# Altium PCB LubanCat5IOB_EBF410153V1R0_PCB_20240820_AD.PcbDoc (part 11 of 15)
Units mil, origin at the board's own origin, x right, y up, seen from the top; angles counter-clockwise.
Board outline 6811.02 x 4055.12 mil, 6 copper layers (TOP, GND02, ART03, ART04, PWR05, BOTTOM), stack 59.279 mil thick; 981 components, 783 nets, 3627 pads, 2669 vias.
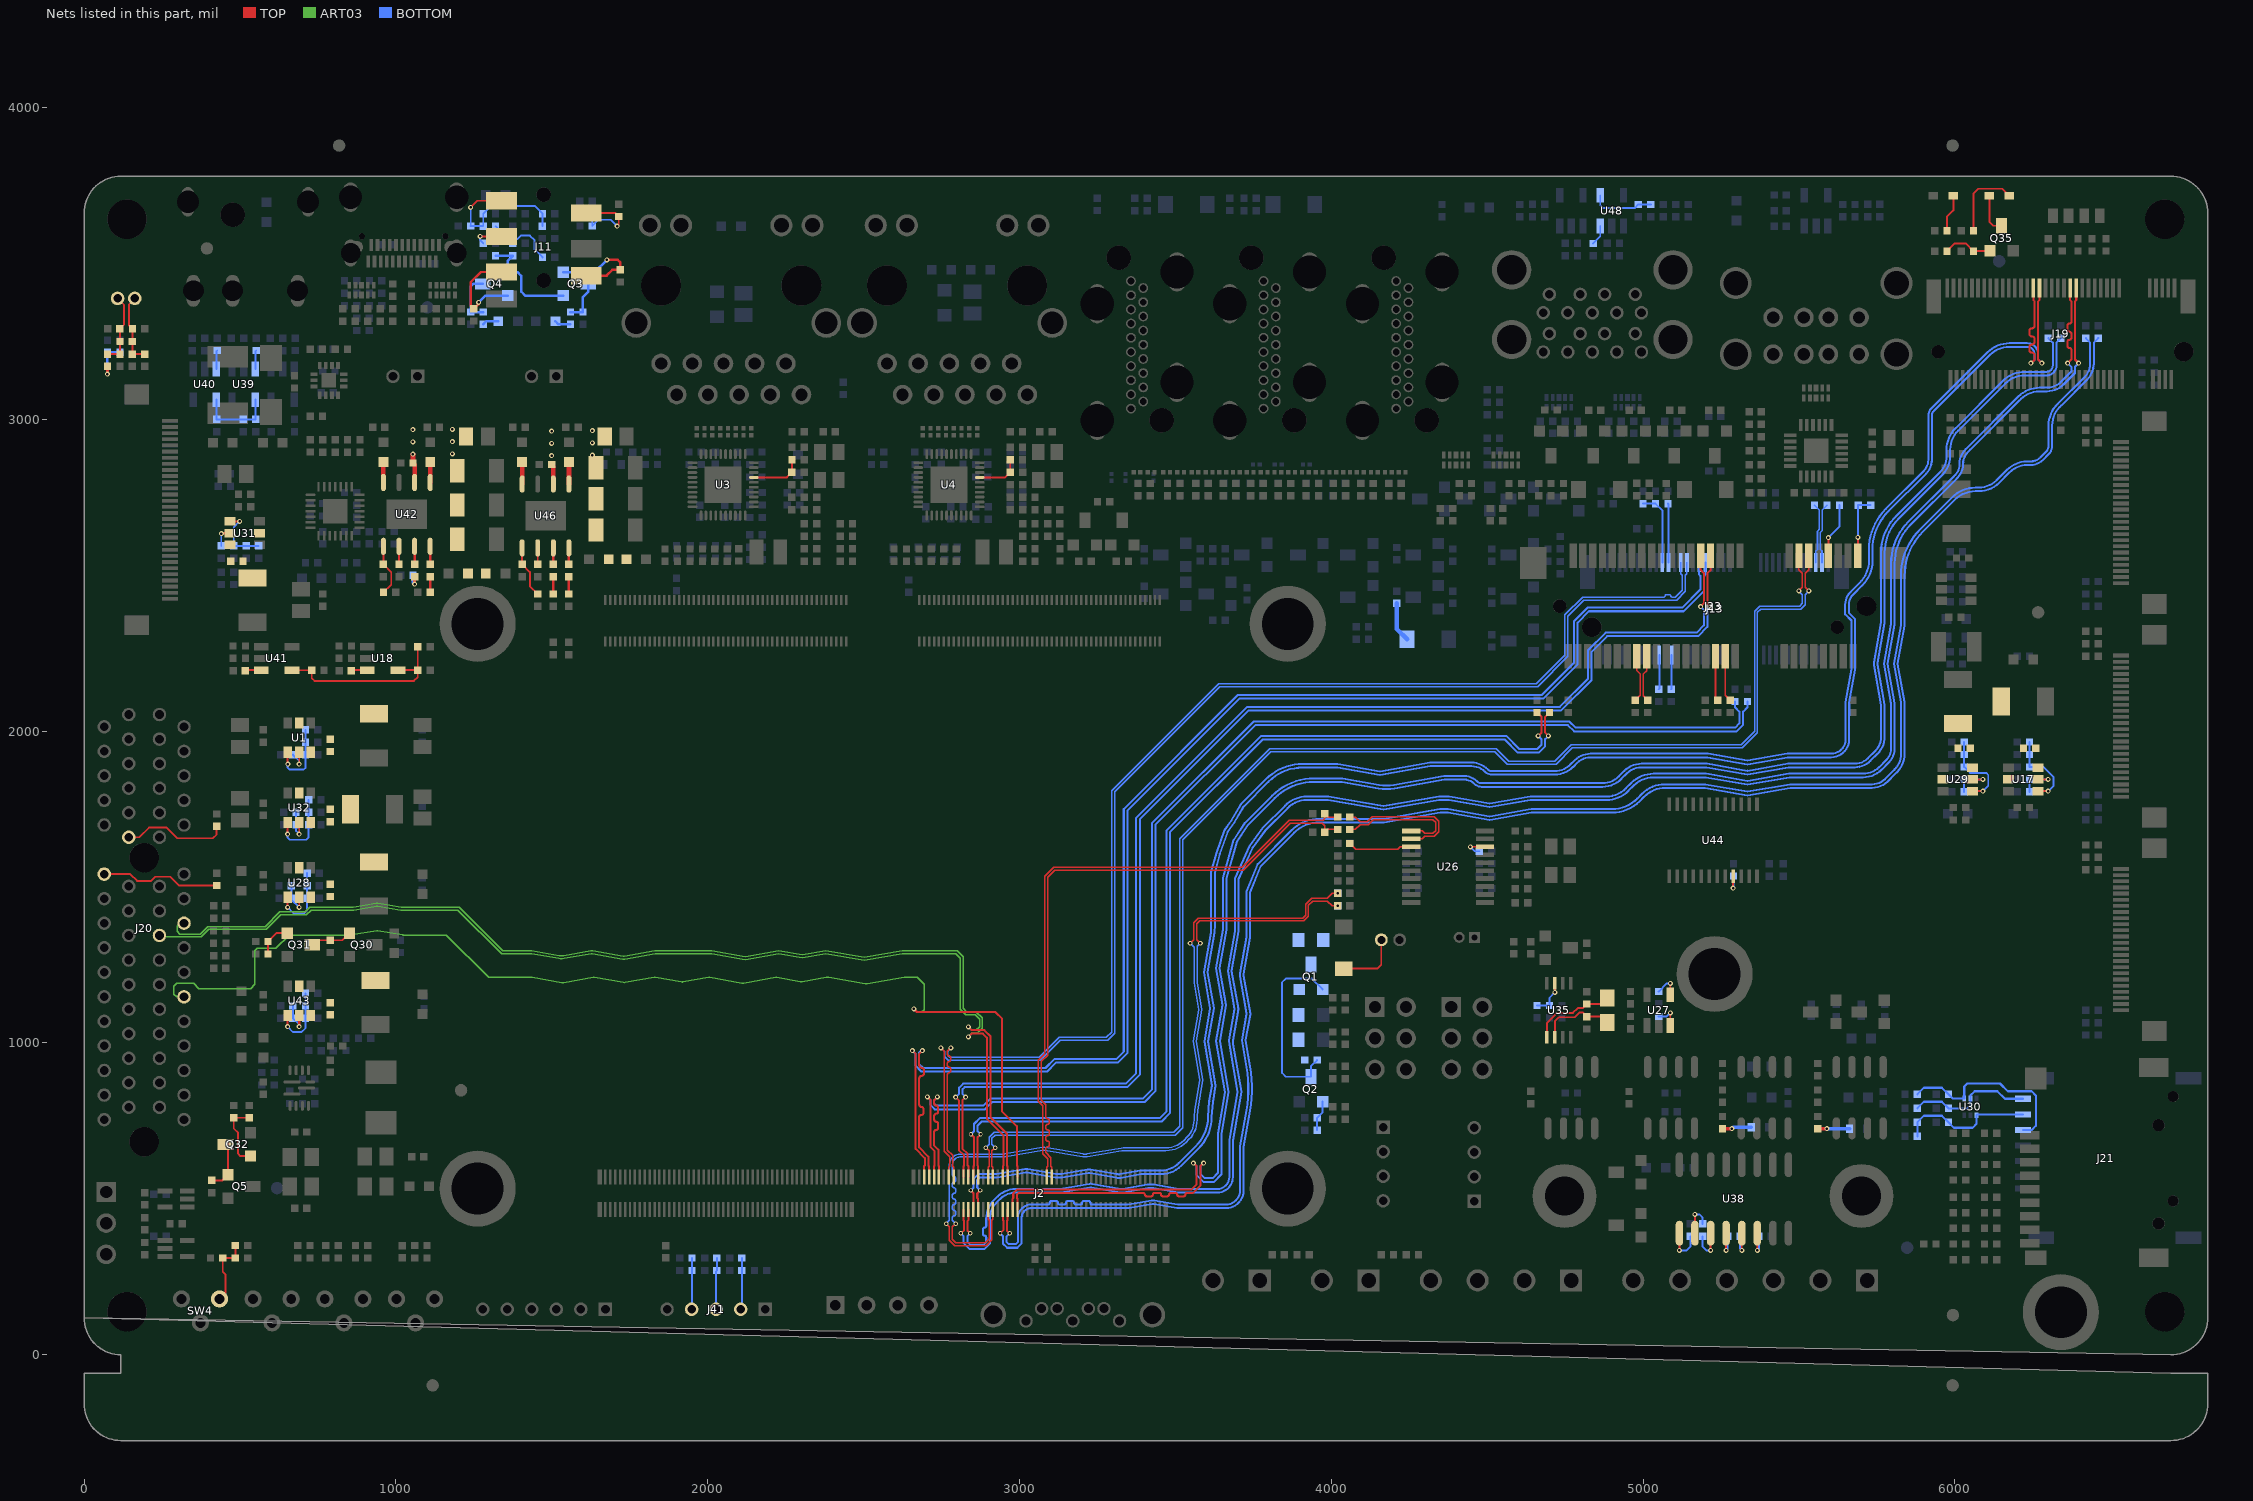
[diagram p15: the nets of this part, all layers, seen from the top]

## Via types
v1: diameter 16, hole 8, TOP to BOTTOM, 2357 vias
v2: diameter 14, hole 8, TOP to BOTTOM, 308 vias
v3: diameter 20, hole 10, TOP to BOTTOM, 4 vias

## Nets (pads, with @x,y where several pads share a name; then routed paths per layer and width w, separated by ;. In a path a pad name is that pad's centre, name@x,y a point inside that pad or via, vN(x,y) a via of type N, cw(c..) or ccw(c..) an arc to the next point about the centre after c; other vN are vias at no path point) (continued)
N16810480: R239.1 U26.13 | length 208.2
  TOP w4.5: R239.1@4059.68,1639.37 4078.12,1620.93 4213.39,1620.93 4221.43,1628.98 U26.13@4256.89,1628.98
N16810864: R242.1 U26.12 | length 434.5
  TOP w4.5: R242.1@4059.68,1724.37 4077.41,1724.37 4092.66,1709.12 4115.12,1709.12 4131.5,1725.5 4329.82,1725.5 4344.39,1710.94 4344.39,1677.18 4329.82,1662.61 4300.4,1662.61 4292.35,1654.57 U26.12@4256.89,1654.57
N16810873: R243.1 U26.11 | length 403
  TOP w4.5: R243.1@4059.68,1684.37 4077.41,1684.37 4092.66,1699.62 4119.06,1699.62 4135.44,1716 4325.89,1716 4334.89,1707 4334.89,1681.11 4325.89,1672.11 4300.4,1672.11 4292.35,1680.16 U26.11@4256.89,1680.16
N16814949: C188.1 U27.4 | length 85.1
  TOP w6: U27.4@5087.4,1154.21 v1(5087.4,1191)
  BOTTOM w6: C188.1@5050,1164.68 5076.32,1191 v1(5087.4,1191)
N16815530: R246.1 U27.3 | length 82.9
  TOP w6: U27.3@5087.4,1055.79 v1(5087.4,1096.4)
  BOTTOM w6: R246.1@5050,1084.68 5075.68,1084.68 v1(5087.4,1096.4)
N16823880: J20.B11 R247.2 | length 340
  TOP w6: J20.B11@143.3,1659.44 177.07,1659.44 208.13,1690.5 264.87,1690.5 299,1656.37 413,1656.37 425,1668.37 R247.2@425,1694.69
N16823920: J20.B12 R248.2 | length 386.9
  TOP w6: J20.B12@64.56,1541.33 148.04,1541.33 170,1519.37 215.22,1519.37 228.86,1533.02 276.35,1533.02 304.68,1504.69 R248.2@425,1504.69
N16831021: Q30.1 Q31.3 R255.2 | length 135.5
  TOP w6: Q31.3@731.5,1314.37 746.18,1329.05 R255.2@790,1329.05 828.68,1329.05 Q30.1@851.5,1351.87
N16831025: Q31.1 R256.2 R257.1 | length 112.9
  TOP w6: R257.1@589.68,1285 R256.2@589.68,1325 616.55,1351.87 Q31.1@651.5,1351.87
N16835418: C194.1 R249.1 R250.1 U28.4 | length 226.9
  TOP w6: v1(652.6,1434.37) U28.4@652.6,1467.13
  BOTTOM w6: v1(652.6,1434.37) 671.6,1415.37 706,1415.37 715.32,1424.69 R249.1@715.32,1464.37 C194.1@715.32,1504.37 R250.1@715.32,1544.37
N16835425: C179.2 L17.1 U28.2
N16835491: C179.1 U28.6
N16835549: R251.1 R252.1 U28.5 | length 113.2
  TOP w6: v1(690,1434.37) U28.5@690,1467.13
  BOTTOM w6: R252.1@664.68,1504.37 R251.1@664.68,1464.37 664.68,1459.69 v1(690,1434.37)
N16843509: C199.1 L18.1 U29.2
N16843563: R262.2 R263.1 U29.5 | length 132.3
  TOP w6: U29.5@6057.24,1845 v1(6089.6,1845)
  BOTTOM w6: R263.1@6029.68,1805 R262.2@6029.68,1845 v1(6089.6,1845)
N16843694: C209.1 J21.2 R258.2 U30.4 | length 605.9
  BOTTOM w6.8: R258.2@5879.68,835 5900.88,856.2 5958.48,856.2 C209.1@5979.68,835 5993.1,821.58 U30.4@6030.31,821.58 6030.31,860.32 6039.93,869.93 6145.07,869.93 6170,845 6246.4,845 6260,831.4 6260,734.39 6246.4,720.79 J21.2@6218.9,720.79
N16843698: C208.1 J21.3 R259.2 U30.5 | length 408
  BOTTOM w6.8: R259.2@5879.68,790 5900.88,811.2 5958.48,811.2 C208.1@5979.68,790 6040,790 6050,800 U30.5@6050,821.58 6050,831.4 6063.6,845 6136.57,845 6160.79,820.79 J21.3@6218.9,820.79
N16843753: C200.2 R254.2 R261.1 U29.4 | length 259.2
  TOP w6: U29.4@6057.24,1807.6 v1(6089.6,1807.6)
  BOTTOM w6: R261.1@6029.68,1885 6048.68,1866 6100.2,1866 6107,1859.2 6107,1825 v1(6089.6,1807.6) ; R254.2@6029.68,1925 C200.2@6029.68,1965
  BOTTOM w6.8: R261.1@6029.68,1885 R254.2@6029.68,1925
N16843960: J23.1 R264.2 R265.2 | length 202.9
  TOP w6: J23.1@5688.98,2562.26 v1(5688.98,2621.37)
  BOTTOM w6: v1(5688.98,2621.37) 5690,2622.39 R264.2@5690,2724.69 R265.2@5730,2724.69
N16843974: J23.7 R266.2 | length 177.1
  TOP w6: J23.7@5594.49,2562.26 v1(5594.49,2620.37)
  BOTTOM w6: v1(5594.49,2620.37) 5630,2655.88 R266.2@5630,2724.69
N16843993: C199.2 U29.6
N16844137: J23.20 R267.1 | length 147.1
  TOP w6: J23.20@5263.78,2239.43 5263.78,2115.27 R267.1@5280,2099.05
N16844170: C207.1 J21.7 R253.2 R260.2 U30.1 | length 443.5
  BOTTOM w6.8: R253.2@5879.68,700 R260.2@5879.68,745 5900.88,766.2 5958.48,766.2 C207.1@5979.68,745 5997.08,727.6 6057.21,727.6 6069.69,740.08 U30.1@6069.69,768.42 6072.05,770.79 J21.7@6218.9,770.79
N16844211: J23.22 R268.1 | length 143.6
  TOP w6: J23.22@5232.28,2239.43 5232.28,2106.76 R268.1@5240,2099.05
N16844471: J23.38 R270.1 | length 151.7
  TOP w5.2: R270.1@4975,2099.05 4991.36,2115.41 4991.36,2182.93 4980.32,2193.98 J23.38@4980.32,2239.43
N16844509: J23.36 R269.1 | length 150.9
  TOP w5.2: J23.36@5011.81,2239.43 5011.81,2193.98 5000.77,2182.93 5000.77,2113.28 R269.1@5015,2099.05
N16890924: R65.1 U31.5 | length 67.6
  TOP w8: v1(440,2633.03) 441.97,2635 U31.5@467.76,2635
  BOTTOM w6: R65.1@440,2594.05 v1(440,2633.03)
N16890968: C224.1 U31.6
N16890980: C224.2 L20.1 U31.2
N16890990: C225.1 R36.1 R271.1 U31.4 | length 196.7
  TOP w6: U31.4@467.76,2672.4 v1(498.47,2672.4)
  BOTTOM w6: v1(498.47,2672.4) 480,2653.93 C225.1@480,2594.05 R36.1@520,2594.05 R271.1@560,2594.05
N16891594: R6.1 U1.5 | length 76.2
  TOP w6: v1(690,1894.37) U1.5@690,1932.13
  BOTTOM w6: R6.1@669.68,1924.37 690,1904.05 v1(690,1894.37)
N16891638: C6.1 U1.6
N16891644: C6.2 L2.1 U1.2
N16891660: C7.1 R4.1 R7.1 U1.4 | length 234.3
  TOP w6: U1.4@652.6,1932.13 652.6,1895.37 v1(653.6,1894.37)
  BOTTOM w6: v1(653.6,1894.37) 652.6,1893.37 652.6,1883.17 659.4,1876.37 703.52,1876.37 710.32,1883.17 R4.1@710.32,1924.37 C7.1@710.32,1964.37 R7.1@710.32,2004.37
N16892291: C14.2 L21.1 U32.2
N16892293: C232.1 R272.1 R274.1 U32.4 | length 242.6
  TOP w6: v1(652.6,1669.37) U32.4@652.6,1707.13
  BOTTOM w6: v1(652.6,1669.37) 652.6,1658.17 659.4,1651.37 712,1651.37 720.32,1659.69 R272.1@720.32,1699.37 C232.1@720.32,1739.37 R274.1@720.32,1779.37
N16892339: C14.1 U32.6
N16892349: C239.1 R273.1 U32.5 | length 112
  TOP w6: v1(690,1669.37) U32.5@690,1707.13
  BOTTOM w6: C239.1@679.68,1739.37 R273.1@679.68,1699.37 679.68,1679.69 v1(690,1669.37)
N16906360: C241.1 U35.2 Y5.2 | length 243.6
  TOP w6: U35.2@4717.2,1018.39 4717.2,1069.2 4730,1082 4780.8,1082 4796.4,1097.6 4806.45,1097.6 C241.1@4820,1084.05 4866.55,1084.05 Y5.2@4885,1065.6
N16906384: C240.1 U35.1 Y5.1 | length 272
  TOP w6: U35.1@4691.61,1018.39 4691.61,1063.41 4724.2,1096 4775,1096 4790.6,1111.6 4806.91,1111.6 C240.1@4820,1124.69 4865.29,1124.69 Y5.1@4885,1144.4
N16906410: R276.2 R277.1 U35.7 | length 119.1
  TOP w6: v1(4717.2,1161.8) U35.7@4717.2,1191.61
  BOTTOM w6: R277.1@4660,1119.68 R276.2@4700,1119.68 4700,1144.59 v1(4717.2,1161.8)
N16921467: D58.1 R287.2 | length 102.2
  TOP w12: R287.2@5560,724.69 v1(5590,724.69)
  BOTTOM w12: v1(5590,724.69) 5590.32,724.37 D58.1@5662.05,724.37
N16921931: D60.1 R293.2 | length 94
  TOP w12: R293.2@5255,724.69 v1(5285,724.69)
  BOTTOM w12: v1(5285,724.69) 5289.68,729.37 D60.1@5347.05,729.37
N16922864: C247.1 U38.3 | length 118.3
  TOP w6: v1(5216.78,334.57) U38.3@5216.78,389.57
  BOTTOM w6: C247.1@5191.26,379.37 5191.26,346.57 5203.26,334.57 v1(5216.78,334.57)
N16922866: C247.2 U38.1 | length 127.9
  TOP w6: v1(5116.78,334.57) U38.1@5116.78,389.57
  BOTTOM w6: v1(5116.78,334.57) 5139.89,334.57 5151.9,346.57 C247.2@5151.9,379.37
N16922868: C248.1 U38.5 | length 102.1
  TOP w6: v1(5316.78,334.57) U38.5@5316.78,389.57
  BOTTOM w6: C248.1@5311.26,379.37 5311.26,340.09 v1(5316.78,334.57)
N16922870: C248.2 U38.4 | length 102.1
  TOP w6: v1(5266.37,334.57) U38.4@5266.37,389.57
  BOTTOM w6: v1(5266.37,334.57) 5271.9,340.09 C248.2@5271.9,379.37
N16922872: C246.1 U38.6 | length 102.1
  TOP w6: v1(5366.37,334.57) U38.6@5366.37,389.57
  BOTTOM w6: v1(5366.37,334.57) 5371.9,340.09 C246.1@5371.9,379.37
N16922874: C245.1 U38.2 | length 109.3
  TOP w6: U38.2@5166.37,389.57 v1(5166.37,449.57)
  BOTTOM w6: v1(5166.37,449.57) 5181.37,449.57 5191.26,439.69 C245.1@5191.26,419.37
N16935603: C128.1 R138.1 R141.1 U17.4 | length 255.1
  TOP w6.8: U17.4@6267.24,1807.6 v1(6299.6,1807.6)
  BOTTOM w6: C128.1@6239.68,1965 R138.1@6239.68,1925 R141.1@6239.68,1885 6284.21,1885 6317,1852.21 6317,1825 v1(6299.6,1807.6)
N16935613: C127.2 L25.1 U17.2
N16935675: C127.1 U17.6
N16935717: R139.1 R140.1 U17.5 | length 132.3
  TOP w6.8: U17.5@6267.24,1845 v1(6299.6,1845)
  BOTTOM w6: R139.1@6239.68,1805 R140.1@6239.68,1845 v1(6299.6,1845)
N16966626: C259.1 C262.1 R306.2 U39.4 U40.4 | length 252.4
  BOTTOM w6: U40.4@424.4,3063.16 425,3062.56 C262.1@425,2999.68 R306.2@510,2999.68 C259.1@550,2999.68 549.4,3000.28 U39.4@549.4,3063.16
N16966707: C258.1 C265.1 R305.2 U18.4 U41.4 | length 598.1
  TOP w6: U41.4@666.84,2195.6 667.44,2195 C265.1@730.32,2195 730.32,2169.68 739,2161 1058,2161 1070.32,2173.32 C258.1@1070.32,2195 ; U18.4@1006.84,2195.6 1069.72,2195.6 C258.1@1070.32,2195 ; R305.2@1070.32,2270 C258.1@1070.32,2195
N16966725: R307.1 U18.3 | length 52.2
  TOP w6: R307.1@857.31,2193 859.91,2195.6 U18.3@908.42,2195.6
N16966842: R310.1 U41.3 | length 52.2
  TOP w6: R310.1@517.31,2193 519.91,2195.6 U41.3@568.42,2195.6
N16967089: R308.1 U39.3 | length 60.2
  BOTTOM w6: U39.3@549.4,3161.58 549.4,3218.09 R308.1@552,3220.69
N16967190: R309.1 U40.3 | length 60.2
  BOTTOM w6: U40.3@424.4,3161.58 424.4,3218.09 R309.1@427,3220.69
N17015969: R323.1 U48.3 | length 65.5
  BOTTOM w6: R323.1@4840,3564.05 4862.6,3586.65 U48.3@4862.6,3620.16
N17016021: C284.1 R324.2 U48.4 | length 203.1
  BOTTOM w6: U48.4@4862.6,3718.58 4862.6,3686.77 4872.22,3677.16 4973.1,3677.16 C284.1@4985,3689.05 R324.2@5025,3689.05
N17044511: J13.55 R147.2 R148.2 | length 238.1
  BOTTOM w6: R148.2@5000,2729.69 R147.2@5040,2729.69 5062.09,2707.6 J13.55@5062.09,2540.77
N17044551: J13.53 R145.2 | length 189.7
  BOTTOM w6: R145.2@5080,2729.69 5081.77,2727.92 J13.53@5081.77,2540.77
N17044654: J13.52 R144.1 | length 110.1
  BOTTOM w6: R144.1@5090,2134.05 5091.62,2135.67 J13.52@5091.62,2243.52
N17044656: J13.56 R146.1 | length 110.4
  BOTTOM w6: R146.1@5050,2134.05 5052.25,2136.3 J13.56@5052.25,2243.52
N17044766: J13.3 R142.2 | length 194.9
  BOTTOM w5.2: J13.3@5573.9,2540.77 5573.9,2577.41 5568.76,2582.56 5568.76,2637.26 5574.7,2643.21 5574.7,2709.39 R142.2@5590,2724.69
N17044768: J13.5 R143.2 | length 194.9
  BOTTOM w5.2: R143.2@5550,2724.69 5565.3,2709.39 5565.3,2647.1 5559.36,2641.16 5559.36,2582.56 5554.21,2577.41 J13.5@5554.21,2540.77
N17083881: Q5.1 Q32.3 R319.2 | length 159.7
  TOP w6: R319.2@410,559.05 443.68,559.05 Q5.1@461.5,576.87 461.5,666.37 Q32.3@453.5,674.37
N17083895: Q32.1 R320.2 R321.1 | length 213.7
  TOP w6: R321.1@530,759.69 R320.2@480,759.69 480,725.37 494,711.37 494,644.37 501.5,636.87 Q32.1@533.5,636.87
N17085595: C290.1 R316.1 R322.1 U43.4 | length 217.2
  TOP w6.8: v1(652.6,1051.97) U43.4@652.6,1087.13
  BOTTOM w6: v1(652.6,1051.97) 670,1034.57 697.21,1034.57 710.32,1047.68 R316.1@710.32,1079.37 C290.1@710.32,1119.37 R322.1@710.32,1159.37
N17085599: C283.2 L26.1 U43.2
N17085653: C283.1 U43.6
N17085706: R317.1 R318.1 U43.5 | length 111
  TOP w6.8: v1(690,1051.97) U43.5@690,1087.13
  BOTTOM w6: R317.1@669.68,1119.37 R318.1@669.68,1079.37 690,1059.05 v1(690,1051.97)
N17139366: Q1.1 Q2.3 R132.2 | length 599.9
  BOTTOM w6: R132.2@3954.68,945 3935,925.32 Q2.3@3935,891.5 3854,891.5 3842,903.5 3842,1194 3854,1206 3938,1206 Q1.1@3972.5,1171.5
N17139370: Q2.1 R133.2 R135.1 | length 98.9
  BOTTOM w6: R133.2@3954.68,720 R135.1@3954.68,760 3972.5,777.82 Q2.1@3972.5,811.5
N17139392: D15.1 J12.1 R129.2 | length 205.7
  TOP w6: D15.1@4040,1238.07 4148.07,1238.07 4160.47,1250.47 J12.1@4160.47,1330.6
N17139440: Q1.2 R127.2 R131.2 R132.1
N17139454: Q1.3 R129.1
N17140097: C126.1 D83.2 P1.1 R126.2 R130.1 | length 233.1
  TOP w6: R126.2@75,3209.05 R130.1@115,3209.05 115.32,3209.37 C126.1@115.32,3249.37 114.68,3250.01 D83.2@114.68,3290 128,3303.32 128,3367.16 P1.1@107.44,3387.72
N17140111: C126.2 D78.2 P1.2 R134.1 R136.1 | length 231.4
  TOP w6: P1.2@162.56,3387.72 144,3369.16 144,3301.32 D78.2@155.32,3290 155.32,3250.01 C126.2@154.68,3249.37 155,3249.05 R134.1@155,3209.05 R136.1@195,3209.05
N17140177: C125.1 R125.2 R126.1 | length 134.4
  TOP w10: v1(75,3145) R126.1@75,3169.69
  BOTTOM w8: v1(75,3145) C125.1@75,3214.69 R125.2@115,3214.69
N17141731: C210.1 C211.1 C218.1 C219.1 C278.1 R341.2 R342.2 U42.6 | length 93.2
  TOP w15: v1(1054.68,2888.32) C278.1@1054.68,2860 1060,2854.68 U42.6@1060,2797.36
  other v1: 1181,2889 1054.68,2927.69 1181,2928.37 1054.68,2967.06 1181,2967.74
N17141824: C303.1 C304.1 C305.1 C306.1 C307.1 R347.2 R348.2 U46.6 | length 64.8
  TOP w15: C307.1@1499.68,2855 1505,2849.68 U46.6@1505,2792.36
  other v1: 1499.68,2883.32 1630,2885 1499.68,2922.69 1630,2924.37 1499.68,2962.06 1630,2963.74
N17141906: R345.2 R346.1 U42.1 | length 168.4
  TOP w6: U42.1@960,2592.64 R346.1@960,2534.68 960.32,2534.68 985,2510 985,2469.68 R345.2@960.32,2445
N17141982: R343.2 U42.4 | length 58
  TOP w8: R343.2@1110,2534.68 U42.4@1110,2592.64
N17142014: C279.2 R343.1 | length 50.5
  TOP w8: C279.2@1109.68,2445 1110,2445.32 R343.1@1110,2495.32
N17142016: R344.2 U42.3 | length 58
  TOP w8: R344.2@1060,2534.68 U42.3@1060,2592.64
N17142030: C299.2 R344.1 | length 55.5
  TOP w10: v1(1060,2471) R344.1@1060,2495.32
  BOTTOM w8: C299.2@1054.68,2500 1054.68,2476.32 v1(1060,2471)
N17142049: L19.1 U42.5 | length 66.1
  TOP w15: U42.5@1110,2797.36 L19.1@1110,2863.5
N17142051: L27.1 U42.8 | length 66.1
  TOP w15: U42.8@960,2797.36 L27.1@960,2863.5
N17142055: C302.1 U42.2 | length 58
  TOP w6: C302.1@1010,2534.68 U42.2@1010,2592.64
N17142188: R351.2 R352.1 U46.1 | length 168.7
  TOP w6: U46.1@1405,2587.64 R352.1@1405,2534.68 1430,2509.68 1430,2464.68 R351.2@1455,2439.68
N17142262: R349.2 U46.4 | length 53
  TOP w8: R349.2@1555,2534.68 U46.4@1555,2587.64
N17142284: R350.2 U46.3 | length 53
  TOP w8: R350.2@1505,2534.68 U46.3@1505,2587.64
N17142286: C308.2 R349.1 | length 55.6
  TOP w8: C308.2@1555,2439.68 R349.1@1555,2495.32
N17142298: C309.2 R350.1 | length 55.6
  TOP w8: C309.2@1505,2439.68 R350.1@1505,2495.32
N17142317: L28.1 U46.5 | length 71.1
  TOP w15: U46.5@1555,2792.36 L28.1@1555,2863.5
N17142331: L29.1 U46.8 | length 71.1
  TOP w15: U46.8@1405,2792.36 L29.1@1405,2863.5
N17142348: C312.1 U46.2 | length 53
  TOP w6: C312.1@1455,2534.68 U46.2@1455,2587.64
N17143919: C288.1 D81.2 J11.6 R119.2 R120.1 | length 319
  TOP w6: J11.6@1610.24,3661.42 1703.9,3661.42 D81.2@1715,3650.32 1715,3625 v1(1709.37,3619.37)
  BOTTOM w6: R120.1@1590,3659.69 R119.2@1630,3659.69 1629.68,3659.37 C288.1@1629.68,3620 1649.68,3640 1688.74,3640 v1(1709.37,3619.37)
N17143960: J11.2 R327.1 | length 95.1
  TOP w6: v1(1270,3586.61) J11.2@1338.6,3586.61
  BOTTOM w6: v1(1270,3586.61) 1270,3574.69 R327.1@1280.32,3564.37
N17143962: C116.1 D82.2 J11.1 R114.1 R115.2 R116.1 | length 499
  TOP w6: v1(1240,3679.37) 1261.41,3700.78 J11.1@1338.6,3700.78
  BOTTOM w6: v1(1240,3679.37) 1240,3620.32 D82.2@1239.68,3620 1279.69,3620 R115.2@1280.32,3619.37 R116.1@1280.32,3659.37 1305.32,3684.37 1445.32,3684.37 C116.1@1470.32,3659.37 1470,3659.05 R114.1@1470,3619.05
N17143973: C111.1 R113.1 R115.1 | length 230.2
  BOTTOM w6: R115.1@1319.68,3619.37 1320.32,3619.37 C111.1@1375.32,3564.37 1400.32,3589.37 1430,3589.37 1445,3574.37 1445,3544.69 R113.1@1470.32,3519.37
N17144006: D79.2 J11.4 Q3.2 | length 344.4
  TOP w8: J11.4@1610.24,3460.63 1675.63,3460.63 1694.68,3479.68 D79.2@1720,3479.68 1720,3503 1711.5,3511.5 v1(1676.5,3511.5)
  BOTTOM w8: Q3.2@1536.5,3471.87 1636.87,3471.87 v1(1676.5,3511.5)
N17144062: C289.1 Q3.1 Q4.1 R326.1 | length 353.8
  BOTTOM w8: R326.1@1319.68,3524.37 C289.1@1375.32,3524.37 1358.5,3507.55 Q4.1@1358.5,3471.87 1390,3471.87 1402,3459.87 1402,3409.37 1414.5,3396.87 Q3.1@1536.5,3396.87
N17144068: C287.2 R124.2 | length 52.5
  BOTTOM w8: R124.2@1280,3304.69 1289.68,3314.37 C287.2@1328.5,3314.37
N17144070: C122.2 R122.2 | length 52.5
  BOTTOM w8: C122.2@1511.5,3314.37 1521.18,3304.69 R122.2@1560,3304.69
N17144072: Q3.3 R122.1 R123.1 | length 137.2
  BOTTOM w8: R122.1@1560,3344.05 R123.1@1600,3344.05 1600,3392 1616.5,3408.5 Q3.3@1616.5,3434.37
N17144086: Q4.3 R124.1 R325.1 | length 164.1
  BOTTOM w8: Q4.3@1278.5,3434.37 1248,3434.37 1240,3426.37 R325.1@1240,3344.05 R124.1@1280,3344.05
N17144157: D80.2 J11.3 Q4.2 | length 330.6
  TOP w8: v1(1265,3375) 1265,3369.68 D80.2@1250,3354.68 1240,3364.68 1240,3440 1272.44,3472.44 J11.3@1338.6,3472.44
  BOTTOM w8: v1(1265,3375) 1286.87,3396.87 Q4.2@1358.5,3396.87
N17145436: D25.1 J41.2 R338.2 | length 165.9
  BOTTOM w6: J41.2@2105.94,145.66 2109.68,149.4 D25.1@2109.68,270 R338.2@2109.68,310
N17145440: D47.1 J41.3 R339.2 | length 165.4
  BOTTOM w6: J41.3@2027.2,145.66 2027.2,267.52 D47.1@2029.68,270 R339.2@2029.68,310
N17145452: D48.1 J41.4 R340.2 | length 164.8
  BOTTOM w6: J41.4@1948.46,145.66 1949.68,146.88 D48.1@1949.68,270 R340.2@1949.68,310
N17149601: LED1.2 R11.2 | length 120.8
  TOP w6: R11.2@5974.68,3604.37 5974.68,3649.05 5995.44,3669.81 LED1.2@5995.44,3716.54
N17201409: R353.2 U44.21 | length 77.6
  TOP w6: v1(5288.98,1496.02) U44.21@5288.98,1533.86
  BOTTOM w6: v1(5288.98,1496.02) 5290,1497.05 R353.2@5290,1535.32
N17255856: D49.1 R354.1 | length 129
  BOTTOM w15: R354.1@4210,2409.69 4210,2327.44 D49.1@4243.07,2294.37
N17266822: Q35.1 R334.2 R335.1 | length 159.2
  TOP w6: R334.2@5974.68,3539.37 5999.68,3564.37 6034.68,3564.37 R335.1@6059.68,3539.37 6111,3539.37 Q35.1@6112.5,3540.87
N17266886: LED2.2 R128.2 | length 251
  TOP w6: R128.2@6059.68,3604.37 6059.68,3724.05 6075,3739.37 6152.37,3739.37 LED2.2@6175.2,3716.54
N17266888: LED2.1 Q35.3 | length 127.6
  TOP w6: LED2.1@6111.01,3716.54 6111.01,3632.87 6123.01,3620.87 Q35.3@6150,3620.87
N17604055: R384.2 R385.1 U4.37 | length 144.7
  TOP w6: U4.37@2872.43,2813.62 2953.94,2813.62 R385.1@2970,2829.68 2970.32,2830 R384.2@2970.32,2870
N17605387: R386.1 R387.2 U3.37 | length 169.1
  TOP w6: U3.37@2148.02,2813.62 2253.94,2813.62 R386.1@2270,2829.68 2270,2869.68 R387.2@2270.32,2870
OE: R223.2 U26.8 | length 82
  TOP w6: v1(4446.02,1628.98) U26.8@4493.11,1628.98
  BOTTOM w6: v1(4446.02,1628.98) 4460.32,1614.68 R223.2@4475,1614.68
ON/OFF: C28.1 D6.2 R19.1 SW4.2 | length 223.9
  TOP w6: SW4.2@434.14,178.81 453.94,198.62 453.94,256.06 444.68,265.32 D6.2@444.68,310 C28.1@485.32,310 R19.1@485.32,350
PCIE20_1_REFCLKN: J2.15 J13.49 | length 4087.9
  TOP w4.5: v1(2780.33,984) 2769,972.67 2769,963.17 ccw(c2774,963.17) 2774,958.17 cw(c2774,953.17) 2779,953.17 2779,945.17 cw(c2774,945.17) 2774,940.17 ccw(c2774,935.17) 2769,935.17 2769,927.17 ccw(c2774,927.17) 2774,922.17 cw(c2774,917.17) 2779,917.17 2779,909.17 cw(c2774,909.17) 2774,904.17 ccw(c2774,899.17) 2769,899.17 2769,656 2785.86,639.14 2785.86,604.01 2788.98,600.88 J2.15@2788.98,569.96
  BOTTOM w4.5: v1(2780.33,984) 2769.7,973.36 2769.7,959.74 2775.93,953.5 3063.06,953.5 3127.56,1018 3279,1018 3295.5,1034.5 3295.5,1808.94 3638.43,2151.87 4658.06,2151.87 4749.5,2243.31 4749.5,2372.94 4806.43,2429.87 5066.6,2429.87 ccw(c5066.6,2433.93) 5070.66,2433.93 cw(c5074.73,2433.93) 5074.73,2438 5084.6,2438 cw(c5084.6,2433.93) 5088.66,2433.93 ccw(c5092.73,2433.93) 5092.73,2429.87 5103.87,2429.87 5126.23,2452.24 5126.23,2499.23 5121.14,2504.32 J13.49@5121.14,2540.77
PCIE20_1_REFCLKP: J2.13 J13.47 | length 4087.9
  TOP w4.5: v1(2748.17,984) 2759.5,972.67 2759.5,652.06 2776.36,635.21 2776.36,604.01 2773.23,600.88 J2.13@2773.23,569.96
  BOTTOM w4.5: v1(2748.17,984) 2760.2,971.98 2760.2,955.8 2772,944 3067,944 3131.5,1008.5 3282.94,1008.5 3305,1030.56 3305,1805 3642.37,2142.37 4662,2142.37 4759,2239.37 4759,2369 4810.37,2420.37 5107.81,2420.37 5135.73,2448.3 5135.73,2499.23 5140.83,2504.32 J13.47@5140.83,2540.77
PCIE20_1_RXN: J2.5 J13.43 | length 4275.6
  TOP w6.5: v1(2688.86,975) 2678.5,964.64 2678.5,928.01 ccw(c2686.25,928.01) 2686.25,920.26 cw(c2686.25,912.51) 2694,912.51 2694,902.01 cw(c2686.25,902.01) 2686.25,894.26 ccw(c2686.25,886.51) 2678.5,886.51 2678.5,801.57 ccw(c2685.25,801.57) 2685.25,794.82 cw(c2685.25,788.07) 2692,788.07 2692,775.57 cw(c2685.25,775.57) 2685.25,768.82 ccw(c2685.25,762.07) 2678.5,762.07 2678.5,664.76 2708.12,635.15 2708.12,606.42 2710.24,604.3 J2.5@2710.24,569.96
  BOTTOM w6.5: v1(2688.86,975) 2684,975 2677.5,968.5 2677.5,932.5 2690.5,919.5 3083.5,919.5 3112,948 3310.74,948 3334.5,971.76 3334.5,1749.76 3700.61,2115.87 4675.76,2115.87 4778.5,2218.61 4778.5,2352.6 4821.77,2395.87 5125.24,2395.87 5184.29,2454.92 5184.29,2497.41 5180.2,2501.5 J13.43@5180.2,2540.77
PCIE20_1_RXP: J2.3 J13.41 | length 4276.9
  TOP w6.5: v1(2656.64,975) 2667,964.64 2667,660 2696.62,630.38 2696.62,606.42 2694.49,604.3 J2.3@2694.49,569.96
  BOTTOM w6.5: v1(2656.64,975) 2666,965.64 2666,927.74 2685.74,908 3088.26,908 3116.76,936.5 3315.5,936.5 3346,967 3346,1745 3705.37,2104.37 4680.52,2104.37 4790,2213.85 4790,2347.84 4826.53,2384.37 5130,2384.37 5195.79,2450.16 5195.79,2497.41 5199.88,2501.5 J13.41@5199.88,2540.77
PCIE20_1_TXN: C252.1 J2.9 | length 4008
  TOP w6.5: v1(2736.98,827) 2726.61,816.64 2726.61,805.14 ccw(c2732.81,805.14) 2732.81,798.94 cw(c2732.81,792.75) 2739,792.75 2739,779.14 cw(c2732.81,779.14) 2732.81,772.94 ccw(c2732.81,766.75) 2726.61,766.75 2726.61,753.14 ccw(c2732.81,753.14) 2732.81,746.94 cw(c2732.81,740.75) 2739,740.75 2739,727.14 cw(c2732.81,727.14) 2732.81,720.94 ccw(c2732.81,714.75) 2726.61,714.75 2726.61,670.65 2739.61,657.65 2739.61,606.42 2741.74,604.3 J2.9@2741.74,569.96
  BOTTOM w6.5: v1(2736.98,827) 2726.61,816.64 2726.61,805 2733.11,798.5 2884.24,798.5 2907.74,822 3396.74,822 3424.5,849.76 3424.5,1703.76 3751.61,2030.87 4763.76,2030.87 4783.76,2010.87 5295.24,2010.87 5309.25,2024.88 5309.25,2062.29 5295,2076.54 C252.1@5295,2094.69
PCIE20_1_TXP: C251.1 J2.7 | length 4017.9
  TOP w6.5: v1(2704.75,827) 2715.11,816.64 2715.11,665.89 2728.11,652.89 2728.11,606.42 2725.99,604.3 J2.7@2725.99,569.96
  BOTTOM w6.5: v1(2704.75,827) 2715.11,816.64 2715.11,800.24 2728.35,787 2889,787 2912.5,810.5 3401.5,810.5 3436,845 3436,1699 3756.37,2019.37 4759,2019.37 4779,1999.37 5300,1999.37 5320.75,2020.12 5320.75,2062.29 5335,2076.54 C251.1@5335,2094.69
PCIE20_2_REFCLKN: J2.31 J23.11 | length 4421.6
  TOP w4.5: J2.31@2914.97,569.96 2914.97,600.88 2911.84,604.01 2911.84,653.41 v2(2922.43,664) ; J23.11@5531.5,2562.26 5531.5,2516.96 5520.5,2505.96 5520.5,2460.73 v1(5531.86,2449.37)
  BOTTOM w4.5: v2(2922.43,664) 2911.84,674.59 2911.84,693.41 2922.44,704 3499,704 3523,728 3523,1651.56 3805.94,1934.5 4525.06,1934.5 4565.19,1894.37 4721,1894.37 4773.5,1946.87 5318.5,1946.87 5367,1995.37 5367,2380.37 5378,2391.37 5505.94,2391.37 5520.5,2405.93 5520.5,2438.01 v1(5531.86,2449.37)
PCIE20_2_REFCLKP: J2.29 J23.13 | length 4421.6
  TOP w4.5: v2(2891.75,664) 2902.34,653.41 2902.34,604.01 2899.22,600.88 J2.29@2899.22,569.96 ; v1(5499.64,2449.37) 5511,2460.73 5511,2505.96 5500,2516.96 J23.13@5500,2562.26
  BOTTOM w4.5: v2(2891.75,664) 2902.34,674.59 2902.34,697.34 2918.5,713.5 3495.06,713.5 3513.5,731.94 3513.5,1655.5 3802,1944 4529,1944 4569.13,1903.87 4717.06,1903.87 4769.56,1956.37 5314.56,1956.37 5357.5,1999.31 5357.5,2384.31 5374.06,2400.87 5502,2400.87 5511,2409.87 5511,2438.01 v1(5499.64,2449.37)
PCIE20_2_RXN: J2.21 J23.23 | length 4073.9
  TOP w6.5: v1(2827.36,826) 2817,815.64 2817,661 2834.1,643.9 2834.1,606.42 2836.23,604.3 J2.21@2836.23,569.96 ; J23.23@5216.54,2562.26 5216.54,2516.55 5206.54,2506.55 5206.54,2409.58 v1(5216.9,2399.21)
  BOTTOM w6.5: v1(2827.36,826) 2817.92,835.44 2817.92,851.5 2824.42,858 3346,858 3386,898 3386,1716.74 3735.63,2066.37 4737.6,2066.37 4835,2163.77 4835,2254.37 4885,2304.37 5176.54,2304.37 5206.54,2334.37 5206.54,2388.85 v1(5216.9,2399.21)
PCIE20_2_RXP: J2.19 J23.25 | length 4074.6
  TOP w6.5: v1(2795.14,826) 2805.5,815.64 2805.5,656.24 2822.6,639.13 2822.6,606.42 2820.48,604.3 J2.19@2820.48,569.96 ; v1(5184.68,2399.21) 5195.04,2409.58 5195.04,2506.55 5185.04,2516.55 J23.25@5185.04,2562.26
  BOTTOM w6.5: v1(2795.14,826) 2806.42,837.28 2806.42,856.26 2819.66,869.5 3341.24,869.5 3374.5,902.76 3374.5,1721.5 3730.87,2077.87 4732.84,2077.87 4823.5,2168.53 4823.5,2259.13 4880.24,2315.87 5171.77,2315.87 5195.04,2339.13 5195.04,2388.85 v1(5184.68,2399.21)
PCIE20_2_TXN: C214.1 J2.25 | length 3183.4
  TOP w6.5: J2.25@2867.72,569.96 2867.72,604.3 2865.6,606.42 2865.6,697.42 v2(2875.18,707) ; v1(4696.11,1984.37) 4685.75,1994.73 4685.75,2045.44 C214.1@4700,2059.69
  BOTTOM w6.5: v2(2875.18,707) 2865.6,716.58 2865.6,734.96 2878.6,747.96 3455.96,747.96 3482.5,774.5 3482.5,1675.5 3780,1973 4556.74,1973 4598.61,1931.12 4666.01,1931.12 4685.75,1950.86 4685.75,1974.01 v1(4696.11,1984.37)
PCIE20_2_TXP: C215.1 J2.23 | length 3183.4
  TOP w6.5: v2(2844.52,707) 2854.1,697.42 2854.1,606.42 2851.97,604.3 J2.23@2851.97,569.96 ; C215.1@4660,2059.69 4674.25,2045.44 4674.25,1994.73 v1(4663.89,1984.37)
  BOTTOM w6.5: v2(2844.52,707) 2854.1,716.58 2854.1,739.73 2873.83,759.46 3451.2,759.46 3471,779.26 3471,1680.27 3775.24,1984.5 4561.5,1984.5 4603.38,1942.62 4661.25,1942.62 4674.25,1955.62 4674.25,1974.01 v1(4663.89,1984.37)
PCIE30_PORT0_REF_CLKN: J2.32 R217.2 R219.1 | length 2529.8
  TOP w4.5: v2(2764.91,420.22) 2775.5,409.63 2775.5,366.5 2792,350 2893.68,350 2911.84,368.16 2911.84,431.57 2914.97,434.69 J2.32@2914.97,465.62 ; v1(3547.75,1319.55) 3559.11,1330.91 3559.11,1385.94 3573.68,1400.5 3908.5,1400.5 3917.5,1409.5 3917.5,1444.94 3936.68,1464.12 3987.34,1464.12 4002.59,1479.37 v1(4020.32,1479.37)
  BOTTOM w4.5: v2(2764.91,420.22) 2775.5,430.81 2775.5,610 cw(c2809,610) 2809,643.5 2950.67,643.5 ccw(c2950.67,652.5) 2952.21,643.63 3075.06,664.96 cw(c3078.22,646.74) 3081.39,664.96 3204.24,643.63 ccw(c3205.78,652.5) 3205.78,643.5 3214.77,643.5 ccw(c3214.77,652.5) 3216.31,643.63 3326.88,662.83 cw(c3339.43,590.53) 3339.43,663.91 ccw(c3340.98,672.79) 3339.9,663.85 ccw(c3340.98,672.79) 3340.98,663.78 3469.53,663.78 ccw(c3469.53,746.46) 3528,688 3536.86,696.86 ccw(c3480.73,753) 3560.12,753 3560.11,765.05 3561.72,783.83 3578.76,881.91 3557.4,1004.92 3575.11,1106.92 3560.11,1193.28 3560.11,1307.18 v1(3547.75,1319.55)
PCIE30_PORT0_REF_CLKP: J2.30 R216.2 R220.1 | length 2527.4
  TOP w4.5: v2(2795.59,420.22) 2785,409.63 2785,370.44 2795.94,359.5 2889.75,359.5 2902.34,372.09 2902.34,431.57 2899.22,434.69 J2.30@2899.22,465.62 ; v1(3579.98,1319.55) 3568.61,1330.91 3568.61,1382 3577.61,1391 3912.44,1391 3927,1405.56 3927,1441 3940.62,1454.62 3987.34,1454.62 4002.59,1439.37 v1(4020.32,1439.37)
  BOTTOM w4.5: v2(2795.59,420.22) 2785,430.81 2785,440.31 cw(c2790,440.31) 2790,445.31 ccw(c2790,450.31) 2795,450.31 2795,458.31 ccw(c2790,458.31) 2790,463.31 cw(c2790,468.31) 2785,468.31 2785,476.31 cw(c2790,476.31) 2790,481.31 ccw(c2790,486.31) 2795,486.31 2795,494.31 ccw(c2790,494.31) 2790,499.31 cw(c2790,504.31) 2785,504.31 2785,512.31 cw(c2790,512.31) 2790,517.31 ccw(c2790,522.31) 2795,522.31 2795,530.31 ccw(c2790,530.31) 2790,535.31 cw(c2790,540.31) 2785,540.31 2785,548.31 cw(c2790,548.31) 2790,553.31 ccw(c2790,558.31) 2795,558.31 2795,566.31 ccw(c2790,566.31) 2790,571.31 cw(c2790,576.31) 2785,576.31 2785,610 cw(c2809,610) 2809,634 2950.67,634 ccw(c2950.67,652.5) 2953.84,634.27 3076.68,655.6 cw(c3078.22,646.74) 3079.76,655.6 3202.61,634.27 ccw(c3205.78,652.5) 3205.78,634 3214.77,634 ccw(c3214.77,652.5) 3217.94,634.27 3328.5,653.47 cw(c3339.43,590.53) 3338.79,654.41 ccw(c3340.97,672.79) 3340.98,654.28 3469.53,654.28 ccw(c3469.53,746.46) 3534.71,681.28 3543.58,690.14 ccw(c3480.73,753) 3569.62,753 3569.61,764.64 3571.16,782.61 3588.4,881.91 3567.04,1004.92 3584.75,1106.92 3569.61,1194.1 3569.61,1309.18 v1(3579.98,1319.55)
PCIE30_PORT0_RX0N: J2.22 J19.41 | length 6204.9
  TOP w6.5: J2.22@2836.23,465.62 2836.23,431.28 2833.76,428.82 2833.76,397.42 v2(2842.34,388.85) ; v1(6361.98,3180) 6373.86,3191.88 6373.86,3222.51 ccw(c6367.43,3222.51) 6367.43,3228.94 cw(c6367.43,3235.38) 6361,3235.38 6361,3248.51 cw(c6367.43,3248.51) 6367.43,3254.94 ccw(c6367.43,3261.38) 6373.86,3261.38 6373.86,3274.51 ccw(c6367.43,3274.51) 6367.43,3280.94 cw(c6367.43,3287.38) 6361,3287.38 6361,3300.51 cw(c6367.43,3300.51) 6367.43,3306.94 ccw(c6367.43,3313.38) 6373.86,3313.38 6373.86,3378.29 6369.77,3382.38 J19.41@6369.77,3421.65
  BOTTOM w6.5: v2(2842.34,388.85) 2832.76,379.27 2832.76,362.5 2844.26,351 2883.74,351 2893.5,360.76 2893.5,376.24 ccw(c2888.25,376.24) 2888.25,381.49 cw(c2888.25,386.74) 2883,386.74 2883,402.24 cw(c2888.25,402.24) 2888.25,407.49 ccw(c2888.25,412.74) 2893.5,412.74 2893.5,436 cw(c2977.43,436) 2918.08,495.35 2930.36,507.63 cw(c2988,450) 2988,531.5 3128.04,531.5 ccw(c3128.04,544.5) 3130.27,531.69 3223.89,547.95 cw(c3228.08,523.81) 3232.27,547.95 3325.9,531.69 ccw(c3328.12,544.5) 3328.12,531.5 ccw(c3328.12,544.5) 3330.34,531.69 3410.99,545.7 cw(c3421.12,487.34) 3431.25,545.69 3511.89,531.69 ccw(c3514.12,544.5) 3514.12,531.5 3635,531.5 ccw(c3635,569.5) 3673,569.5 3673,688.22 3699.99,843.62 3673.78,994.51 3672.62,1008.08 3690.09,1108.71 3668.89,1230.79 3690.93,1357.74 3690.93,1364.15 3691.02,1364.24 3691.02,1527.38 3738.19,1631.95 3780.24,1689.5 3851.87,1761.13 cw(c3922.46,1690.54) 3922.46,1790.37 3990.44,1790.37 4167.89,1759.56 4345.33,1790.37 4378.28,1790.37 4508.31,1767.79 4638.33,1790.37 4882.67,1790.37 ccw(c4882.67,1878.34) 4944.87,1816.13 4962.87,1834.13 cw(c5033.46,1763.54) 5033.46,1863.37 5202.48,1863.37 5335.45,1840.28 5468.41,1863.37 5705.86,1863.37 ccw(c5705.86,1936.13) 5757.31,1884.68 5780.81,1908.18 ccw(c5745.35,1943.64) 5795.5,1943.64 5795.5,2080.38 5794.84,2088.07 5772.67,2215.75 5794.84,2343.42 5795.5,2351.12 5795.5,2538 cw(c5983.24,2538) 5850.49,2670.75 5997.87,2818.13 6000.34,2820.6 ccw(c5964.94,2856) 6015,2856 cw(c6083.49,2856) 6035.06,2904.43 6203.72,3073.09 cw(c6272,3004.8) 6272,3101.37 6296.1,3101.37 ccw(c6296.1,3163.91) 6340.32,3119.69 6373.86,3153.23 6373.86,3168.12 v1(6361.98,3180)
PCIE30_PORT0_RX0P: J2.20 J19.43 | length 6202.7
  TOP w6.5: v2(2811.68,388.85) 2822.26,399.43 2822.26,429.5 2820.48,431.28 J2.20@2820.48,465.62 ; J19.43@6389.45,3421.65 6389.45,3382.38 6385.36,3378.29 6385.36,3191.88 v1(6397.24,3180)
  BOTTOM w6.5: v2(2811.68,388.85) 2821.26,379.27 2821.26,357.74 2839.5,339.5 2888.5,339.5 2905,356 2905,436 cw(c2977.43,436) 2926.21,487.21 2938.5,499.5 cw(c2988,450) 2988,520 3128.04,520 ccw(c3128.04,544.5) 3132.23,520.36 3225.86,536.62 cw(c3228.08,523.81) 3230.31,536.62 3323.93,520.36 ccw(c3328.12,544.5) 3328.12,520 ccw(c3328.12,544.5) 3332.31,520.36 3412.95,534.36 cw(c3421.12,487.34) 3429.28,534.36 3509.93,520.36 ccw(c3514.12,544.5) 3514.12,520 3635,520 ccw(c3635,569.5) 3684.5,569.5 3684.5,687.23 3711.66,843.62 3685.2,995.99 3684.2,1007.58 3701.76,1108.71 3680.56,1230.79 3702.61,1357.74 3702.61,1364.15 3702.52,1364.24 3702.52,1524.9 3748.18,1626.13 3789,1682 3860,1753 cw(c3922.46,1690.54) 3922.46,1778.87 3989.45,1778.87 4167.89,1747.89 4346.32,1778.87 4377.29,1778.87 4508.31,1756.12 4639.32,1778.87 4882.67,1778.87 ccw(c4882.67,1878.34) 4953,1808 4971,1826 cw(c5033.46,1763.54) 5033.46,1851.87 5201.49,1851.87 5335.45,1828.61 5469.4,1851.87 5705.86,1851.87 ccw(c5705.86,1936.13) 5765.44,1876.55 5788.94,1900.05 ccw(c5745.35,1943.64) 5807,1943.64 5807,2080.87 5806.25,2089.55 5784.34,2215.75 5806.25,2341.94 5807,2350.62 5807,2538 cw(c5983.24,2538) 5858.62,2662.62 6006,2810 6008.47,2812.47 ccw(c5964.94,2856) 6026.5,2856 cw(c6083.49,2856) 6043.19,2896.3 6049.45,2902.55 6207.45,3060.55 6211.85,3064.95 cw(c6272,3004.8) 6272,3089.87 6296.1,3089.87 ccw(c6296.1,3163.91) 6348.45,3111.55 6385.36,3148.47 6385.36,3168.12 v1(6397.24,3180)
PCIE30_PORT0_RX1N: J2.26 J19.29 | length 5939.5
  TOP w6.5: J2.26@2867.72,465.62 2867.72,499.97 2864.61,503.08 2864.61,516.99 v2(2874.19,526.57) ; v1(6243.87,3180) 6255.75,3191.88 6255.75,3205.56 ccw(c6247.38,3205.56) 6247.38,3213.93 cw(c6247.38,3222.31) 6239,3222.31 6239,3231.56 cw(c6247.38,3231.56) 6247.38,3239.93 ccw(c6247.38,3248.31) 6255.75,3248.31 6255.75,3257.56 ccw(c6247.38,3257.56) 6247.38,3265.93 cw(c6247.38,3274.31) 6239,3274.31 6239,3283.56 cw(c6247.38,3283.56) 6247.38,3291.93 ccw(c6247.38,3300.31) 6255.75,3300.31 6255.75,3378.29 6251.66,3382.38 J19.29@6251.66,3421.65
  BOTTOM w6.5: v2(2874.19,526.57) 2864.61,536.14 2864.61,559.61 2872.53,567.53 2924.29,567.53 ccw(c2924.29,592.03) 2928.48,567.89 3019.98,583.78 cw(c3022.2,570.97) 3024.43,583.78 3115.93,567.89 ccw(c3120.12,592.03) 3120.12,567.53 3132,567.53 ccw(c3132,592.03) 3136.19,567.89 3220.84,582.59 cw(c3223.06,569.78) 3225.28,582.59 3309.93,567.89 ccw(c3320.05,626.18) 3320.06,567.02 ccw(c3320.06,591.52) 3324.25,567.38 3390.35,578.85 cw(c3394.07,557.44) 3397.78,578.85 3453.39,578.85 ccw(c3453.38,671.73) 3519.06,606.06 3573.82,660.82 ccw(c3471.99,762.65) 3616,762.65 3620.09,810.32 3629.31,863.42 3604.81,1004.5 3623.27,1110.76 3603.22,1226.19 3625.38,1353.82 3626.41,1378.68 3626.41,1546.88 3642.41,1605.04 3668,1677 3689,1707 3718.62,1757.36 ; 3718.63,1757.37 3719,1758 3798.5,1837.5 cw(c3908.35,1727.64) 3908.35,1883 4019.65,1883 4156.01,1859.32 4318.29,1887.5 4449.34,1887.5 cw(c4449.34,1824.34) 4494,1869 ccw(c4514.84,1889.84) 4514.84,1860.37 4716.61,1860.37 ccw(c4716.61,1943.39) 4775.32,1884.69 4788.82,1898.19 cw(c4831.51,1855.49) 4831.51,1915.87 5207.01,1915.87 5335.45,1893.57 5463.89,1915.87 5603.53,1915.87 ccw(c5603.53,1973.34) 5661,1973.34 5661,2050 5661.38,2050.38 5661.38,2086.17 5661.21,2086.34 cw(c5674.02,2088.57) 5661.21,2090.79 5679.64,2196.93 ccw(c5655.5,2201.12) 5680,2201.12 5680,2359.37 5660,2379.37 5660,2405.54 cw(c5705.46,2405.54) 5673.32,2437.69 5703.31,2467.68 ccw(c5624.41,2546.59) 5736,2546.59 5736,2582 cw(c5909.82,2582) 5786.91,2704.91 5787,2705 5908,2826 ccw(c5863.32,2870.67) 5926.5,2870.67 5926.5,3012.01 cw(c5947.01,3012.01) 5932.51,3026.51 6101,3195 6112.16,3206.16 cw(c6176,3142.33) 6176,3232.61 6232.15,3232.61 cw(c6232.15,3209) 6255.75,3209 6255.75,3191.88 v1(6243.87,3180)
PCIE30_PORT0_RX1P: J2.24 J19.31 | length 5937.5
  TOP w6.5: v2(2843.53,526.57) 2853.11,516.99 2853.11,501.11 2851.97,499.97 J2.24@2851.97,465.62 ; J19.31@6271.34,3421.65 6271.34,3382.38 6267.25,3378.29 6267.25,3191.88 v1(6279.13,3180)
  BOTTOM w6.5: v2(2843.53,526.57) 2853.11,536.14 2853.11,564.38 2867.76,579.03 2924.29,579.03 ccw(c2924.28,592.03) 2926.51,579.22 3018.01,595.11 cw(c3022.2,570.97) 3026.39,595.11 3117.9,579.22 ccw(c3120.12,592.03) 3120.12,579.03 3132,579.03 ccw(c3132,592.03) 3134.22,579.22 3218.87,593.92 cw(c3223.06,569.78) 3227.25,593.92 3311.9,579.22 ccw(c3320.06,626.18) 3320.06,578.52 ccw(c3320.06,591.52) 3322.28,578.71 3388.38,590.18 cw(c3394.06,557.44) 3398.67,590.35 3453.38,590.35 ccw(c3453.38,671.73) 3510.93,614.19 ; 3510.93,614.19 3565.69,668.96 ccw(c3471.99,762.65) 3604.5,762.65 3604.5,763.14 3608.68,811.8 3617.64,863.42 3593.14,1004.5 3611.59,1110.76 3591.55,1226.19 3613.8,1354.32 3614.91,1378.96 3614.91,1548.43 3631.44,1608.49 3657.68,1682.32 3679.32,1713.22 3708.71,1763.19 3709.83,1765.09 3790.36,1845.63 cw(c3908.35,1727.64) 3908.35,1894.5 4020.64,1894.5 4156.01,1870.99 4317.29,1899 4449.34,1899 cw(c4449.34,1824.34) 4502.13,1877.13 ccw(c4514.84,1889.84) 4514.84,1871.87 4716.61,1871.87 ccw(c4716.61,1943.39) 4767.18,1892.82 4780.68,1906.32 cw(c4831.51,1855.49) 4831.51,1927.37 5208,1927.37 5335.45,1905.24 5462.9,1927.37 5603.53,1927.37 ccw(c5603.53,1973.34) 5649.5,1973.34 5649.5,2084 5649.88,2084.38 cw(c5674.02,2088.57) 5649.88,2092.76 5668.31,2198.9 ccw(c5655.5,2201.12) 5668.5,2201.12 5668.5,2354.61 5648.5,2374.61 5648.5,2405.54 cw(c5705.46,2405.54) 5665.18,2445.82 5695.18,2475.82 ccw(c5624.41,2546.59) 5724.5,2546.59 5724.5,2582 cw(c5909.82,2582) 5778.75,2713.02 5899.86,2834.13 ccw(c5863.32,2870.67) 5915,2870.67 5915,3012.01 cw(c5947.01,3012.01) 5924.37,3034.64 6092.87,3203.13 6104.03,3214.3 cw(c6176,3142.33) 6176,3244.11 6232.15,3244.11 cw(c6232.15,3209) 6267.25,3209 6267.25,3191.88 v1(6279.13,3180)
PCIE30_PORT0_TX0N: C177.1 J2.38 | length 5957.9
  TOP w6.5: J2.38@2962.21,465.62 2962.21,431.28 2959.75,428.82 2959.75,397.42 v2(2968.32,388.85)
  BOTTOM w6.5: v2(2968.32,388.85) 2958.75,379.27 2958.75,360.88 2965.25,354.38 2988.12,354.38 2995.5,361.76 2995.5,439 cw(c3038,439) 3038,481.5 3091.4,481.5 ccw(c3091.4,487.25) 3097.15,487.25 cw(c3102.9,487.25) 3102.9,493 3117.4,493 cw(c3117.4,487.25) 3123.15,487.25 ccw(c3128.9,487.25) 3128.9,481.5 3143.4,481.5 ccw(c3143.4,487.25) 3149.15,487.25 cw(c3154.9,487.25) 3154.9,493 3169.4,493 cw(c3169.4,487.25) 3175.15,487.25 ccw(c3180.9,487.25) 3180.9,481.5 3195.4,481.5 ccw(c3195.4,487.25) 3201.15,487.25 cw(c3206.9,487.25) 3206.9,493 3221.4,493 cw(c3221.4,487.25) 3227.15,487.25 ccw(c3232.9,487.25) 3232.9,481.5 3346.56,481.5 ccw(c3346.56,494.5) 3348.79,481.69 3424.15,494.78 cw(c3428.34,470.64) 3432.53,494.78 3507.9,481.69 ccw(c3510.12,494.5) 3510.12,481.5 3662,481.5 ccw(c3662,527) 3707.5,527 3707.5,663.95 cw(c3732.01,663.95) 3707.86,668.14 3727.97,783.93 ccw(c3330.3,852.99) 3727.97,922.04 3713.01,1008.17 3728.89,1092.78 3725.32,1113.3 3707.86,1213.84 cw(c3732,1218.03) 3707.5,1218.03 cw(c3732.01,1218.04) 3707.86,1222.23 3728.29,1339.85 ccw(c3715.48,1342.08) 3728.29,1344.3 3728.12,1345.28 3728.12,1484.84 3764.2,1573.47 3871.86,1681.13 cw(c3962.29,1590.7) 3962.29,1718.58 4167.89,1718.58 4348.81,1750 4374.8,1750 4508.31,1726.82 4641.81,1750 4901,1750 ccw(c4901,1862.83) 4980.78,1783.05 4996.74,1799 cw(c5070.05,1725.69) 5070.05,1829.37 5199.56,1829.37 5335.45,1805.77 5471.34,1829.37 5735,1829.37 ccw(c5735,1887.91) 5776.39,1846.52 5801.44,1871.56 5806.73,1876.85 ccw(c5756.57,1927) 5827.5,1927 5827.5,2081.75 5826.6,2092.19 5805.15,2215.75 5826.6,2339.3 5827.5,2349.74 5827.5,2499 cw(c6036.97,2499) 5888.85,2647.12 5981.86,2740.13 5991.92,2750.19 cw(c6066,2676.11) 6066,2780.87 6077,2780.87 ccw(c6077,2861.11) 6133.74,2804.37 6166.83,2837.46 cw(c6233,2771.29) 6233,2864.87 6242.85,2864.87 ccw(c6242.85,2910.14) 6274.87,2878.13 6292.37,2895.64 ccw(c6272.75,2915.26) 6300.5,2915.26 6300.5,2980 cw(c6396.75,2980) 6328.69,3048.06 6416.3,3135.67 ccw(c6372.98,3179) 6434.25,3179 6434.25,3246.07 C177.1@6420,3260.32
PCIE30_PORT0_TX0P: C178.1 J2.36 | length 5956.8
  TOP w6.5: v2(2937.67,388.85) 2948.25,399.43 2948.25,429.5 2946.46,431.28 J2.36@2946.46,465.62
  BOTTOM w6.5: v2(2937.67,388.85) 2947.25,379.27 2947.25,356.12 2960.48,342.88 2992.88,342.88 3007,357 3007,439 cw(c3038,439) 3038,470 3346.56,470 ccw(c3346.57,494.5) 3350.76,470.36 3426.12,483.45 cw(c3428.34,470.64) 3430.57,483.45 3505.93,470.36 ccw(c3510.12,494.5) 3510.12,470 3662,470 ccw(c3662,527) 3719,527 3719,663.95 cw(c3732.01,663.95) 3719.19,666.17 3739.3,781.97 ccw(c3330.3,852.99) 3739.3,924 3724.7,1008.09 3740.57,1092.71 3719.19,1215.8 cw(c3732,1218.02) 3719,1218.03 cw(c3732.01,1218.03) 3719.19,1220.26 3739.62,1337.88 ccw(c3715.48,1342.08) 3739.62,1346.27 3739.62,1482.59 3773.98,1566.98 3880,1673 cw(c3962.29,1590.7) 3962.29,1707.08 4168.88,1707.08 4349.8,1738.5 4373.81,1738.5 4508.31,1715.14 4642.8,1738.5 4901,1738.5 ccw(c4901,1862.83) 4988.92,1774.92 5003.19,1789.19 cw(c5072.44,1719.94) 5072.44,1817.87 5198.56,1817.87 5335.45,1794.1 5472.34,1817.87 5735,1817.87 ccw(c5735,1887.91) 5784.53,1838.38 5809.57,1863.43 5814.86,1868.71 ccw(c5756.57,1927) 5839,1927 5839,2082.25 5838.02,2093.67 5816.82,2215.75 5838.02,2337.82 5839,2349.25 5839,2499 cw(c6036.97,2499) 5896.98,2638.98 5990,2732 6000.06,2742.05 cw(c6066,2676.11) 6066,2769.37 6077,2769.37 ccw(c6077,2861.11) 6141.87,2796.24 6174.96,2829.33 cw(c6233,2771.29) 6233,2853.37 6242.85,2853.37 ccw(c6242.85,2910.14) 6283,2870 6300.5,2887.5 ccw(c6272.75,2915.26) 6312,2915.26 6312,2980 cw(c6396.75,2980) 6336.82,3039.93 6340.95,3044.05 6424.44,3127.54 ccw(c6372.98,3179) 6445.75,3179 6445.75,3246.07 C178.1@6460,3260.32
PCIE30_PORT0_TX1N: C175.1 J2.42 | length 5755.4
  TOP w6.5: J2.42@2993.71,465.62 2993.71,499.97 2991.58,502.09 2991.58,512.5 2998.08,519 3396.48,519 cw(c3396.48,513.5) 3401.98,513.5 ccw(c3407.48,513.5) 3407.48,508 3422.48,508 ccw(c3422.48,513.5) 3427.98,513.5 cw(c3433.48,513.5) 3433.48,519 3448.48,519 cw(c3448.48,513.5) 3453.98,513.5 ccw(c3459.48,513.5) 3459.48,508 3474.48,508 ccw(c3474.48,513.5) 3479.98,513.5 cw(c3485.48,513.5) 3485.48,519 3500.48,519 cw(c3500.48,513.5) 3505.98,513.5 ccw(c3511.48,513.5) 3511.48,508 3526.48,508 ccw(c3526.48,513.5) 3531.98,513.5 cw(c3537.48,513.5) 3537.48,519 3557,519 3580,542 3580,603.74 v1(3590.36,614.1)
  BOTTOM w6.5: v1(3590.36,614.1) 3580,603.74 3580,580.5 3594.5,566 3619.74,566 3636.5,582.76 3636.5,709.13 3659.46,841.36 3630.89,1005.92 3651.03,1121.91 3630.59,1239.58 3652.14,1363.66 3652.14,1529.73 3687.05,1650.86 3723.55,1705.82 3810.62,1792.88 cw(c3944.89,1658.61) 3944.89,1848.5 4032.09,1848.5 cw(c4032.1,1823.99) 4036.29,1848.14 4153.79,1827.74 ccw(c4177.3,1963.12) 4200.81,1827.74 4361.5,1855.64 cw(c4365.69,1831.49) 4365.69,1856 4426.41,1856 cw(c4426.41,1798.41) 4467.13,1839.13 ccw(c4482.25,1854.25) 4482.25,1832.87 4869.83,1832.87 ccw(c4869.83,1907.16) 4922.37,1854.63 4940.36,1872.63 cw(c4995.27,1817.72) 4995.27,1895.37 5205.24,1895.37 5335.45,1872.76 5465.65,1895.37 5679.06,1895.37 ccw(c5679.06,1954.94) 5721.18,1912.82 5744.5,1936.14 ccw(c5698.64,1982) 5763.5,1982 5763.5,2080.38 ccw(c5750.5,2080.37) 5763.31,2082.6 5740.92,2211.56 cw(c5765.06,2215.75) 5740.92,2219.94 5763.31,2348.9 ccw(c5750.5,2351.12) 5763.5,2351.12 5763.5,2571.95 cw(c5932.04,2571.95) 5812.86,2691.13 5952.83,2831.09 ccw(c5902.92,2881) 5973.5,2881 5973.5,2902 cw(c6071.91,2902) 6002.32,2971.59 6153.48,3122.75 cw(c6225,3051.23) 6225,3152.37 6294.62,3152.37 ccw(c6294.62,3172) 6314.25,3172 6314.25,3246.07 C175.1@6300,3260.32
PCIE30_PORT0_TX1P: C176.1 J2.40 | length 5755.8
  TOP w6.5: J2.40@2977.96,465.62 2977.96,499.97 2980.08,502.09 2980.08,517.26 2993.32,530.5 3552.24,530.5 3568.5,546.76 3568.5,603.74 v1(3558.14,614.1)
  BOTTOM w6.5: v1(3558.14,614.1) 3568.5,603.74 3568.5,575.74 3589.74,554.5 3624.5,554.5 3648,578 3648,708.13 3671.13,841.36 3642.56,1005.92 3662.7,1121.91 3642.26,1239.58 3663.64,1362.67 3663.64,1528.1 3697.61,1645.97 3732.5,1698.49 3818.75,1784.75 cw(c3944.89,1658.61) 3944.89,1837 4032.09,1837 cw(c4032.09,1823.99) 4034.32,1836.81 4151.82,1816.4 ccw(c4177.3,1963.12) 4202.77,1816.4 4363.47,1844.31 cw(c4365.7,1831.49) 4365.7,1844.5 4426.41,1844.5 cw(c4426.41,1798.41) 4459,1831 ccw(c4482.25,1854.25) 4482.25,1821.37 4869.83,1821.37 ccw(c4869.83,1907.16) 4930.5,1846.5 4948.5,1864.5 cw(c4995.27,1817.72) 4995.27,1883.87 5204.25,1883.87 5335.45,1861.09 5466.65,1883.87 5679.06,1883.87 ccw(c5679.06,1954.94) 5729.32,1904.68 5752.63,1928 ccw(c5698.64,1982) 5775,1982 5775,2080.38 ccw(c5750.5,2080.38) 5774.64,2084.57 5752.25,2213.52 cw(c5765.06,2215.75) 5752.25,2217.97 5774.64,2346.93 ccw(c5750.5,2351.12) 5775,2351.12 5775,2571.95 cw(c5932.04,2571.95) 5821,2683 5960.96,2822.96 ccw(c5902.92,2881) 5985,2881 5985,2902 cw(c6071.91,2902) 6010.46,2963.46 6161.61,3114.61 cw(c6225,3051.23) 6225,3140.87 6294.62,3140.87 ccw(c6294.62,3172) 6325.75,3172 6325.75,3246.07 C176.1@6340,3260.32
PCIE30_PORT1_REF_CLKN: J2.55 R243.2 R244.1 | length 2052.5
  TOP w4.5: J2.55@3103.94,569.96 3103.94,600.88 3100.82,604.01 3100.82,632.18 3084.5,648.5 3084.5,661.09 cw(c3090.25,661.09) 3090.25,666.84 ccw(c3090.25,672.59) 3096,672.59 3096,679.09 ccw(c3090.25,679.09) 3090.25,684.84 cw(c3090.25,690.59) 3084.5,690.59 3084.5,697.09 cw(c3090.25,697.09) 3090.25,702.84 ccw(c3090.25,708.59) 3096,708.59 3096,715.09 ccw(c3090.25,715.09) 3090.25,720.84 cw(c3090.25,726.59) 3084.5,726.59 3084.5,733.09 cw(c3090.25,733.09) 3090.25,738.84 ccw(c3090.25,744.59) 3096,744.59 3096,751.09 ccw(c3090.25,751.09) 3090.25,756.84 cw(c3090.25,762.59) 3084.5,762.59 3084.5,801.94 3070.5,815.94 3070.5,941.06 3090.5,961.06 3090.5,1530.5 3113.5,1553.5 3717.94,1553.5 3868.94,1704.5 3971.5,1704.5 3979.68,1696.32 R244.1@3979.68,1675 3989.05,1684.37 R243.2@4020.32,1684.37
PCIE30_PORT1_REF_CLKP: J2.53 R242.2 R245.1 | length 2022.4
  TOP w4.5: J2.53@3088.19,569.96 3088.19,600.88 3091.32,604.01 3091.32,628.25 3075,644.56 3075,798 3061,812 3061,945 3081,965 3081,1534.44 3109.56,1563 3714,1563 3865,1714 3974,1714 3979.68,1719.68 R245.1@3979.68,1735 3990.31,1724.37 R242.2@4020.32,1724.37
PCIE30_PORT1_RX0N: J2.37 J20.A17 | length 3554
  TOP w6.5: v1(2836.16,1051.36) 2846.53,1041 2887.26,1041 2907,1021.26 2907,761.26 2960.09,708.18 2960.09,606.42 2962.21,604.3 J2.37@2962.21,569.96
  ART03 w4.5: J20.A17@241.73,1344.48 246.21,1340 375.87,1340 399.87,1364 584,1364 631,1411 713,1411 727.9,1425.9 861.23,1425.9 ccw(c861.23,1444) 864.32,1426.17 938.09,1438.98 cw(c939.63,1430.11) 941.17,1438.98 1014.94,1426.17 ccw(c1018.03,1444) 1018.03,1425.9 1199.1,1425.9 1339,1286 1433.45,1286 cw(c1433.44,1277) 1434.99,1285.87 1521.73,1270.81 ccw(c1530.92,1323.76) 1540.12,1270.81 1626.86,1285.87 cw(c1628.4,1277) 1628.4,1286 cw(c1628.4,1277) 1629.94,1285.87 1727.49,1268.93 ccw(c1730.59,1286.76) 1733.69,1268.93 1831.24,1285.87 cw(c1832.78,1277) 1832.78,1286 2012.56,1286 2120.05,1267.34 2227.56,1286 2303.48,1272.82 2379.4,1286 2501.82,1264.74 2624.24,1286 2796.13,1286 2810,1272.13 2810,1107.13 2827.23,1089.9 2858.23,1089.9 2872,1076.13 2872,1051.34 2860.46,1039.8 2847.73,1039.8 v1(2836.16,1051.36)
PCIE30_PORT1_RX0P: J2.35 J20.A16 | length 3553.6
  TOP w6.5: v1(2836.16,1019.14) 2846.53,1029.5 2882.5,1029.5 2895.5,1016.5 2895.5,756.5 2948.59,703.41 2948.59,606.42 2946.46,604.3 J2.35@2946.46,569.96
  ART03 w4.5: J20.A16@320.47,1383.85 307,1383.85 298,1374.85 298,1358.1 307,1349.1 372.1,1349.1 396.1,1373.1 580.23,1373.1 627.23,1420.1 709.23,1420.1 724.13,1435 861.22,1435 ccw(c861.22,1444) 862.76,1435.13 936.53,1447.94 cw(c939.63,1430.11) 942.73,1447.94 1016.5,1435.13 ccw(c1018.04,1444) 1018.04,1435 1202.87,1435 1342.77,1295.1 1433.45,1295.1 cw(c1433.45,1277) 1436.54,1294.83 1523.28,1279.77 ccw(c1530.92,1323.76) 1538.56,1279.77 1625.3,1294.83 cw(c1628.4,1277) 1628.4,1295.1 cw(c1628.4,1277) 1631.5,1294.83 1729.05,1277.89 ccw(c1730.59,1286.76) 1732.13,1277.89 1829.68,1294.83 cw(c1832.78,1277) 1832.78,1295.1 2013.34,1295.1 2120.05,1276.57 2227.56,1295.24 2303.48,1282.06 2379.4,1295.24 2501.82,1273.98 2623.46,1295.1 2799.9,1295.1 2819.1,1275.9 2819.1,1110.9 2831,1099 2862,1099 2881.1,1079.9 2881.1,1047.57 2864.23,1030.7 2847.73,1030.7 v1(2836.16,1019.14)
PCIE30_PORT1_RX1N: J2.41 J20.A22 | length 3644.8
  TOP w6.5: v1(2661,1109.36) 2671.36,1099 2923,1099 2944.5,1077.5 2944.5,779.76 2991.58,732.68 2991.58,606.42 2993.71,604.3 J2.41@2993.71,569.96
  ART03 w4.5: J20.A22@320.47,1147.63 297.15,1147.63 288.15,1156.63 288.15,1182.06 297.15,1191.06 350.94,1191.06 368.1,1173.9 533.77,1173.9 548.1,1188.23 548.1,1294.9 556.1,1302.9 614.77,1302.9 657.77,1345.9 854.23,1345.9 ccw(c854.23,1364) 857.32,1346.17 938.44,1360.25 cw(c939.98,1351.38) 941.52,1360.25 1022.64,1346.17 ccw(c1025.74,1364) 1025.74,1345.9 1162.23,1345.9 1298.13,1210 1435.22,1210 cw(c1435.22,1201) 1436.76,1209.87 1532.07,1193.32 ccw(c1535.17,1211.15) 1538.27,1193.32 1633.57,1209.87 cw(c1635.11,1201) 1635.11,1210 cw(c1635.11,1201) 1636.65,1209.87 1729.56,1193.74 ccw(c1732.67,1211.62) 1735.77,1193.74 1828.68,1209.87 cw(c1830.22,1201) 1830.22,1210 cw(c1830.22,1201) 1831.76,1209.87 1914.63,1195.48 ccw(c1917.72,1213.31) 1920.82,1195.48 2003.68,1209.87 cw(c2005.22,1201) 2005.22,1210 cw(c2005.22,1201) 2006.76,1209.87 2109.62,1192.01 ccw(c2112.72,1209.89) 2115.83,1192.01 2218.68,1209.87 cw(c2220.22,1200.99) 2220.22,1210 cw(c2220.22,1201) 2221.76,1209.87 2297.66,1196.69 ccw(c2300.76,1214.52) 2303.86,1196.69 2379.75,1209.87 cw(c2381.3,1201) 2381.29,1210 2386.73,1210 cw(c2386.73,1201) 2388.27,1209.87 2506.05,1189.42 ccw(c2509.16,1207.3) 2512.26,1189.42 2630.03,1209.87 cw(c2631.57,1201) 2631.57,1210 2672.13,1210 2694.29,1187.84 2694.29,1106.8 2685.29,1097.8 2672.56,1097.8 v1(2661,1109.36)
